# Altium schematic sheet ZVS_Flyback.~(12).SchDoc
size 431 x 279 mm; Date: Not shown in title block; ApprovedBy: Not shown in title block; CheckedBy: Not shown in title block; Author: Not shown in title block; CompanyName: Not shown in title block; Engineer: Not shown in title block; Organization: Not shown in title block; Address1: Not shown in title block; Address2: Not shown in title block; Address3: Not shown in title block; Address4: Not shown in title block; DocumentNumber: 2; Revision: Use project parameter SCH_Rev; SheetNumber: 2; SheetTotal: 2; PageSetup: Record=PageOptions¦CenterHorizontal=True¦CenterVertical=True¦PrintScale=1.00¦XCorrection=1.00¦YCorrection=1.00¦PrintKind=0¦BorderSize=5000000¦LeftOffset=0¦BottomOffset=0¦Orientation=2¦PaperLength=1000¦PaperWidth=1000¦Scale=100¦PaperSource=15¦PrintQuality=600¦MediaType=1¦DitherType=10¦PaperKind=Letter¦PrintScaleMode=1
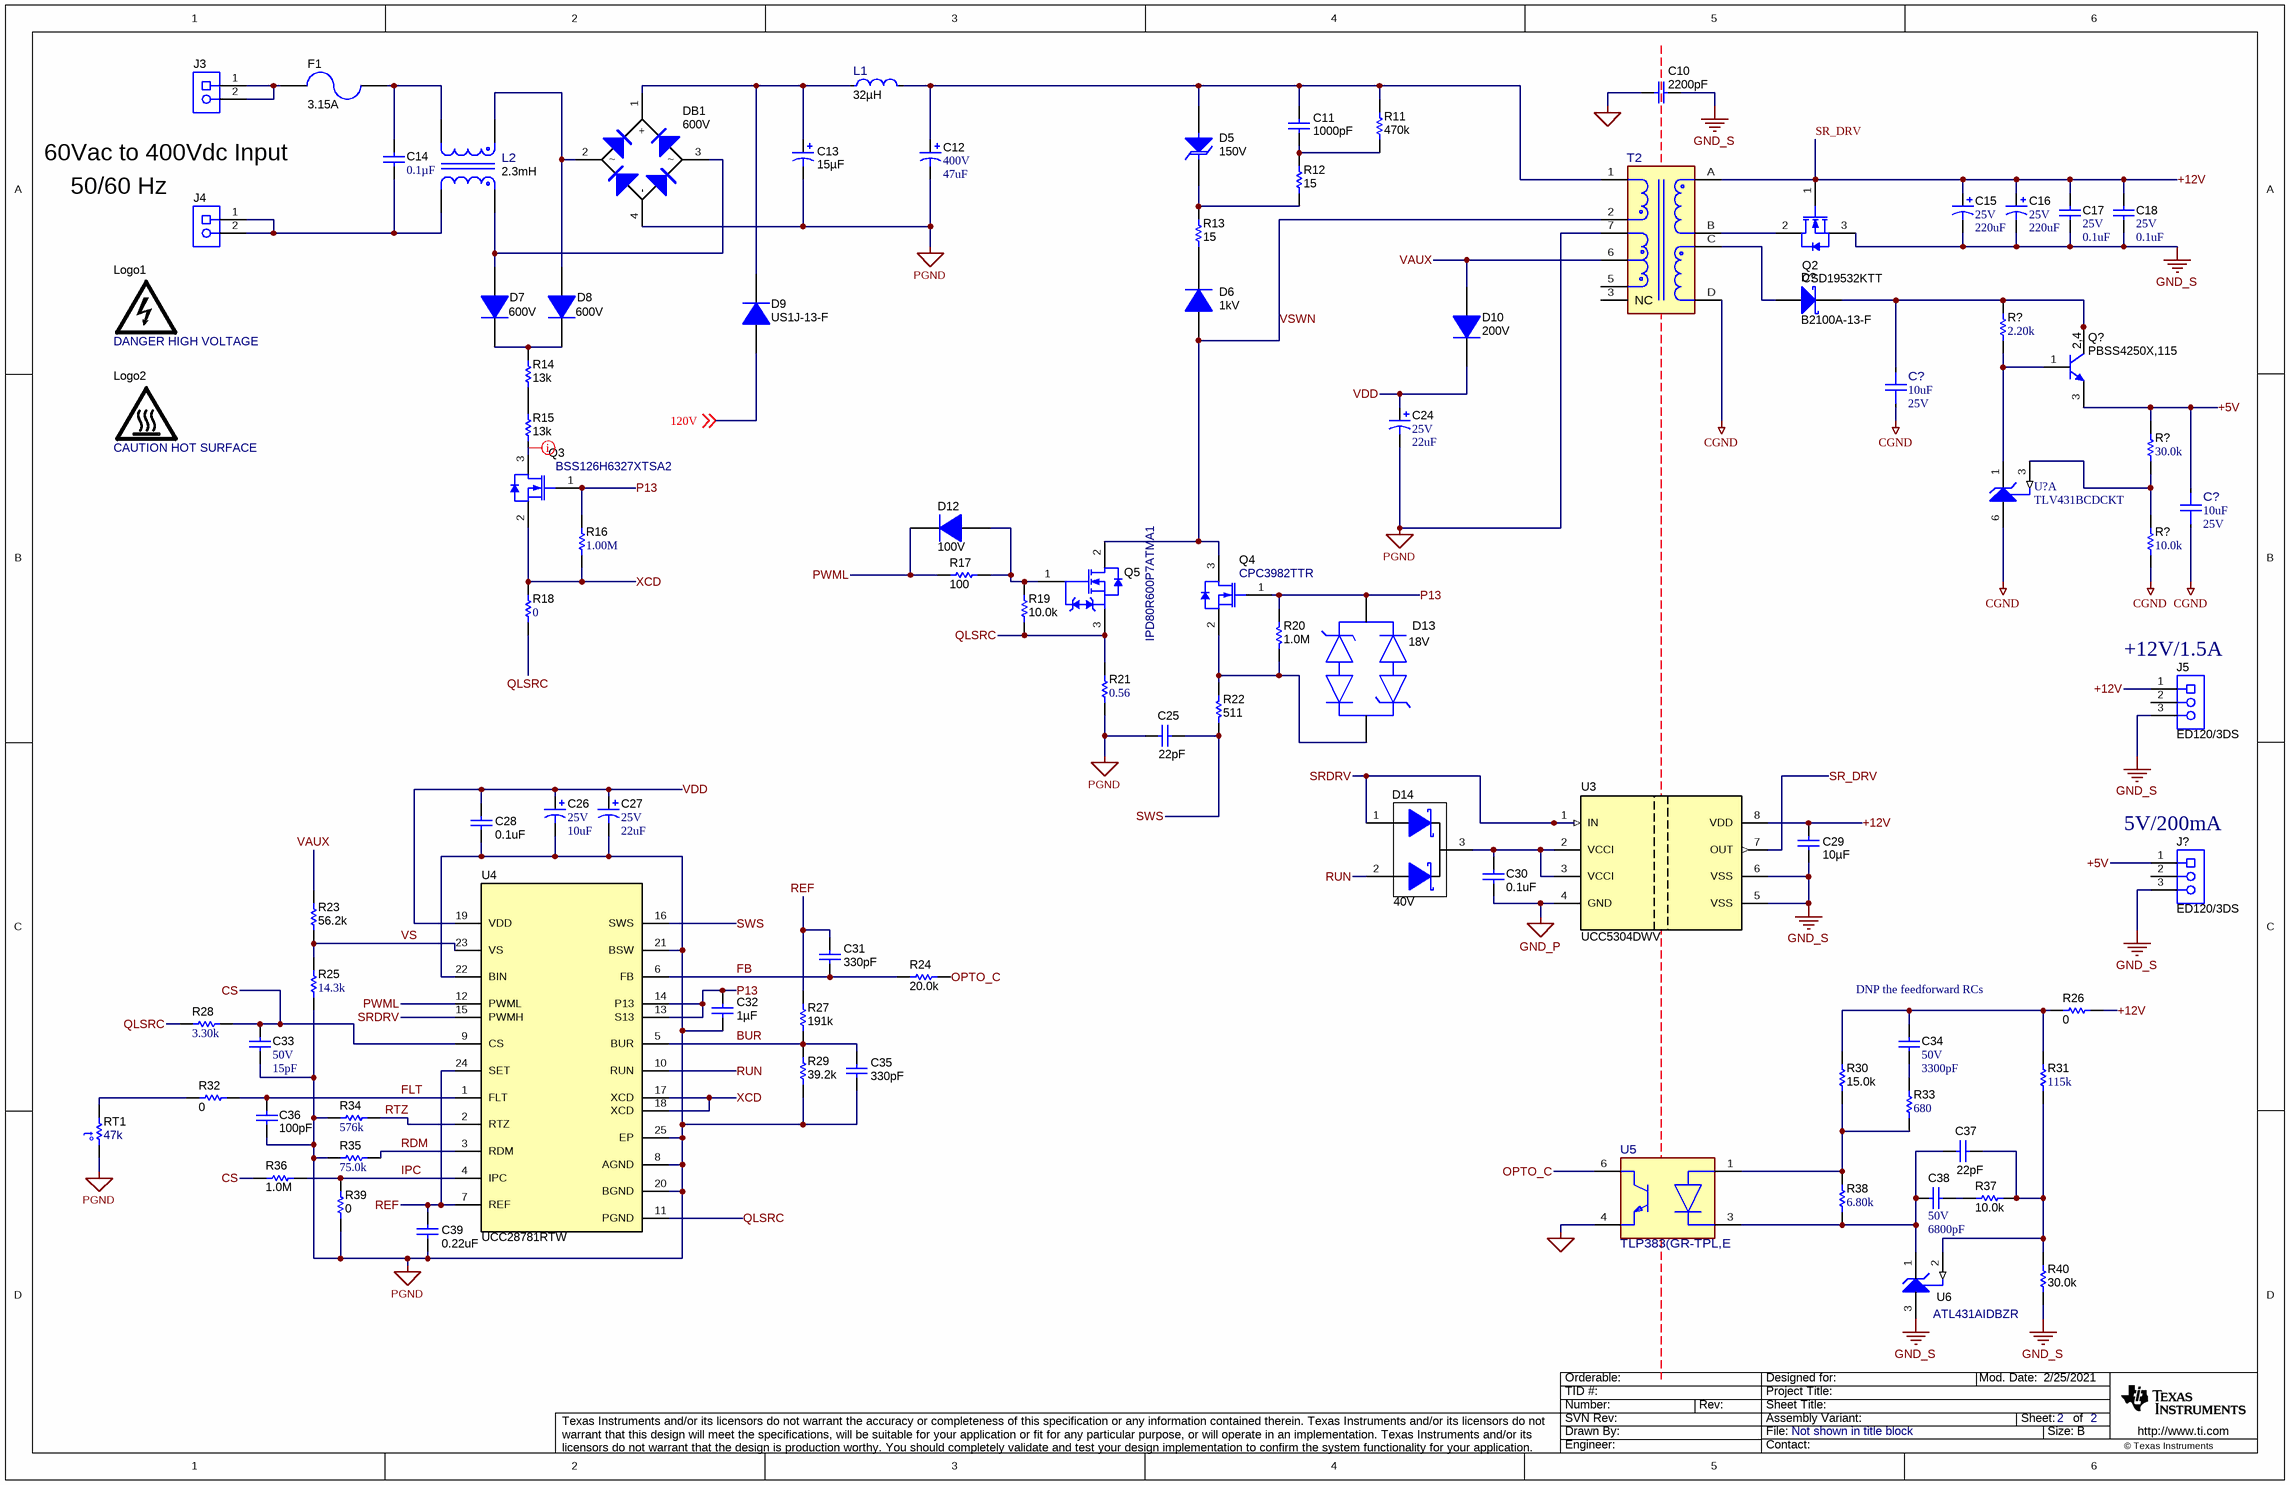
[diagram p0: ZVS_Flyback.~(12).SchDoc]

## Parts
(Parts that share a designator on the sheet are numbered #1, #2 ... from top to bottom, then left to right.)
C10  ValueDisplayed: 2200pF  [C900_9x13]  (hidden comment: C921U222MVVDBA7317)
C11  ValueDisplayed: 1000pF  [1206L]  (hidden comment: GRM31BR72J102KW01L)
C12  VDC_V: 400V  ValueDisplayed: 47uF  [CAPPR7.5-16x25]  (hidden comment: UCS2G470MHD)
C13  ValueDisplayed: 15µF  [UVC_1000x1600]  (hidden comment: UVC2G150MPD)
C14  ValueDisplayed: 0.1µF  [B32933_600x1500x2650]  (hidden comment: B32933A3104K000)
C15  VDC_V: 25V  ValueDisplayed: 220uF  [BT_1000x1250]  (hidden comment: UBT1E221MPD1TD)
C16  VDC_V: 25V  ValueDisplayed: 220uF  [BT_1000x1250]  (hidden comment: UBT1E221MPD1TD)
C17  VDC_V: 25V  ValueDisplayed: 0.1uF  [0603]  (hidden comment: 06033D104KAT2A)
C18  VDC_V: 25V  ValueDisplayed: 0.1uF  [0603]  (hidden comment: 06033D104KAT2A)
C24  VDC_V: 25V  ValueDisplayed: 22uF  [SM_RADIAL_D]  (hidden comment: EEE-FC1E220P)
C25  ValueDisplayed: 22pF  [0402S]  (hidden comment: GCM1555C1H220JA16D)
C26  VDC_V: 25V  ValueDisplayed: 10uF  [CAPSMT_62_D55]  (hidden comment: EMVA250ADA100MD55G)
C27  VDC_V: 25V  ValueDisplayed: 22uF  [SM_RADIAL_D]  (hidden comment: EEE-FC1E220P)
C28  ValueDisplayed: 0.1uF  [0402S]  (hidden comment: GRM155R71H104ME14D)
C29  ValueDisplayed: 10µF  [1206_180L]  (hidden comment: C1206C106J3RACAUTO)
C30  ValueDisplayed: 0.1uF  [0402S]  (hidden comment: GRM155R71H104ME14D)
C31  ValueDisplayed: 330pF  [0402S]  (hidden comment: GRM155R71H331KA01D)
C32  Cap_F: 1µF  [0603S]  (hidden comment: CGA3E1X7R1V105K080AC)
C33  VDC_V: 50V  ValueDisplayed: 15pF  [0402]  (hidden comment: CC0402JRNPO9BN150)
C34  VDC_V: 50V  ValueDisplayed: 3300pF  [0402]  (hidden comment: GRM155R71H332KA01D)
C35  ValueDisplayed: 330pF  [0402S]  (hidden comment: GRM155R71H331KA01D)
C36  ValueDisplayed: 100pF  [0402S]  (hidden comment: GRM1555C1H101JA01D)
C37  ValueDisplayed: 22pF  [0402S]  (hidden comment: GCM1555C1H220JA16D)
C38  VDC_V: 50V  ValueDisplayed: 6800pF  [0402]  (hidden comment: GRM155R71H682KA88D)
C39  ValueDisplayed: 0.22uF  [0402S]  (hidden comment: GRM155R71C224KA12D)
C?#1  ValueDisplayed: 10uF  VDC_V: 25V  [FP-ZRB18AR61E106ME01L_0603-MFG]  (hidden comment: ZRB18AR61E106ME01L)
C?#2  ValueDisplayed: 10uF  VDC_V: 25V  [FP-ZRB18AR61E106ME01L_0603-MFG]  (hidden comment: ZRB18AR61E106ME01L)
D5  VRWM: 150V  [SMA]  (hidden comment: SMAJ150A)
D6  Vr_V: 1kV  [SMA]  (hidden comment: MRA4007T3G)
D7  Vr_V: 600V  [TUMD2SM]  (hidden comment: RFU02VSM6STR)
D8  Vr_V: 600V  [TUMD2SM]  (hidden comment: RFU02VSM6STR)
D9  US1J-13-F  [SMA]
D10  Vr_V: 200V  [SOD-123H]  (hidden comment: CSFMT104-HF)
D12  Vr_V: 100V  [SOD-323]  (hidden comment: BAS316,115)
D13  CDSOD323-T18C  [FP-CDSOD323-T18C_SOD323-MFG]  (value not drawn)
D14  Vr_V: 40V  [SOT-323]  (hidden comment: BAS40W-05-7-F)
D?  B2100A-13-F  [SMA]
DB1  value 600V  [Z4-D]  (hidden comment: Z4DGP406L-HF)
F1  Irating_A: 3.15A  [FUSE_392]  (hidden comment: 39213150000)
J3  ED120/2DS  [On-Shore_ED120_2DS]  (value not drawn)
J4  ED120/2DS  [On-Shore_ED120_2DS]  (value not drawn)
J5  ED120/3DS  [On-Shore_ED120_3DS]
J?  ED120/3DS  [On-Shore_ED120_3DS]
L1  Ind_H: 32µH  [FP-7447052_PTH_D10MM0-MFG]  (hidden comment: 7447052)
L2  Ind_H: 2.3mH  [FP-RLTI-1387_PTH_CMC_0IN38_0IN60-MFG]  (hidden comment: RLTI-1387)
Logo1  DANGER HIGH VOLTAGE  [IEC_HighVoltage_Small]  (no BOM)
Logo2  CAUTION HOT SURFACE  [IEC_HotSurface_Small]  (no BOM)
Q2  CSD19532KTT  [KTT0002A]
Q3  BSS126H6327XTSA2  [SOT-23L]
Q4  CPC3982TTR  [SOT-23L]
Q5  IPD80R600P7ATMA1  [DPAK]
Q?  PBSS4250X,115  [SOT-89-3]
R11  ValueDisplayed: 470k  [0805_HV1]  (hidden comment: CRCW0805470KJNEA)
R12  ValueDisplayed: 15  [0805_HV1]  (hidden comment: CRCW080515R0JNEA)
R13  ValueDisplayed: 15  [0805_HV1]  (hidden comment: CRCW080515R0JNEA)
R14  ValueDisplayed: 13k  [1206L]  (hidden comment: CRCW120613K0JNEA)
R15  ValueDisplayed: 13k  [1206L]  (hidden comment: CRCW120613K0JNEA)
R16  ValueDisplayed: 1.00M  [0603]  (hidden comment: MCT06030C1004FP500)
R17  ValueDisplayed: 100  [0805_HV1]  (hidden comment: CRCW0805100RJNEA)
R18  ValueDisplayed: 0  [0603]  (hidden comment: RC0603JR-070RL)
R19  ValueDisplayed: 10.0k  [0402S]  (hidden comment: CRCW040210K0FKED)
R20  ValueDisplayed: 1.0M  [0402S]  (hidden comment: CRCW04021M00JNED)
R21  ValueDisplayed: 0.56  [1206]  (hidden comment: ERJ-8RQFR56V)
R22  ValueDisplayed: 511  [0402S]  (hidden comment: CRCW0402511RFKED)
R23  ValueDisplayed: 56.2k  [0402S]  (hidden comment: CRCW040256K2FKED)
R24  ValueDisplayed: 20.0k  [0402S]  (hidden comment: CRCW040220K0FKED)
R25  ValueDisplayed: 14.3k  [0402]  (hidden comment: CRCW040214K3FKED)
R26  ValueDisplayed: 0  [0402S]  (hidden comment: RC0402JR-070RL)
R27  ValueDisplayed: 191k  [0402S]  (hidden comment: CRCW0402191KFKED)
R28  ValueDisplayed: 3.30k  [0402]  (hidden comment: RK73H1ETTP3301F)
R29  ValueDisplayed: 39.2k  [0402S]  (hidden comment: CRCW040239K2FKED)
R30  ValueDisplayed: 15.0k  [0402S]  (hidden comment: CRCW040215K0FKED)
R31  ValueDisplayed: 115k  [0402]  (hidden comment: RC1005F1153CS)
R32  ValueDisplayed: 0  [0402S]  (hidden comment: CRCW04020000Z0EDHP)
R33  ValueDisplayed: 680  [0603]  (hidden comment: RC0603FR-07680RL)
R34  ValueDisplayed: 576k  [0402]  (hidden comment: CRCW0402576KFKED)
R35  ValueDisplayed: 75.0k  [0402]  (hidden comment: CRCW040275K0FKED)
R36  ValueDisplayed: 1.0M  [0402S]  (hidden comment: CRCW04021M00JNED)
R37  ValueDisplayed: 10.0k  [0402S]  (hidden comment: CRCW040210K0FKED)
R38  ValueDisplayed: 6.80k  [0603]  (hidden comment: RC0603FR-076K8L)
R39  ValueDisplayed: 0  [0402S]  (hidden comment: CRCW04020000Z0EDHP)
R40  ValueDisplayed: 30.0k  [0402S]  (hidden comment: CRCW040230K0FKED)
R?#1  ValueDisplayed: 2.20k  [0603]  (hidden comment: RC0603FR-072K2L)
R?#2  ValueDisplayed: 30.0k  [0603]  (hidden comment: RC0603FR-0730KL)
R?#3  ValueDisplayed: 10.0k  [0402]  (hidden comment: ERJ-2RKF1002X)
RT1  value 47k  [0603S]  (hidden comment: NCP18WB473J03RB)
T2  RLTI-1324  [FP-RLTI-1324_PTH_0IN980_0IN766-MFG]  (value not drawn)
U3  UCC5304DWV  [DWV0008A]
U4  UCC28781RTW  [RTW0024B]
U5  TLP383(GR-TPL,E  [FP-TLP383(GR-TPL,E_SO6-4-MFG]
U6  ATL431AIDBZR  [DBZ0003A_L]
U?  TLV431BCDCKT  [DCK0006A_N]  (part A of 2)

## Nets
CGND: C?#1.1 C?#2.1 R?#3.1 T2.D U?.6(ANODE)
GND2: C10.2 U5.4(Emitter)
GND_P: C30.2 U3.4(GND)
GND_S: C10.1 C15.2(-) C16.2(-) C17.2 C18.2 C29.2 J5.3 J?.3 Q2.3(S) R40.2 U3.5(VSS) U3.6(VSS) U6.3(ANODE)
PGND: C12.2(-) C13.2(-) C24.2(-) C25.1 C26.2(-) C27.2(-) C28.2 C32.2 C33.2 C35.2 C36.1 C39.2 DB1.4(-) R21.1 R25.1 R29.2 R34.1 R35.1 R39.1 RT1.2 T2.7 U4.8(AGND) U4.20(BGND) U4.21(BSW) U4.22(BIN) U4.25(EP)
120V: D9.2(A) ; off-sheet 120V
+5V: C?#2.2 J?.1 Q?.3(E) R?#2.2
+12V: C15.1(+) C16.1(+) C17.1 C18.1 C29.1 J5.1 Q2.1(G) R26.1 T2.A U3.7(OUT) U3.8(VDD)  [also labelled SR_DRV]
BUR: C35.1 R27.2 R29.1 U4.5(BUR)
CS: C33.1 R28.2 R36.2 U4.9(CS)
FB: C31.2 R24.1 U4.6(FB)
FLT: C36.2 R32.2 U4.1(FLT)
IPC: R36.1 R39.2 U4.4(IPC)
OPTO_C: R24.2 U5.6(Collector)
P13: C32.1 D13.2 Q3.1(G) Q4.1(G) R16.2 R20.2 U4.13(S13) U4.14(P13)
PWML: D12.1(K) R17.1 U4.12(PWML)
QLSRC: Q5.3(S) R18.1 R19.1 R21.2 R28.1 U4.11(PGND)
RDM: R35.2 U4.3(RDM)
REF: C31.1 C39.1 R27.1 U4.7(REF) U4.24(SET)
RTZ: R34.2 U4.2(RTZ)
RUN: D14.2(A) U4.10(RUN)
SRDRV: D14.1(A) U3.1(IN) U4.15(PWMH)
SWS: C25.2 R22.1 U4.16(SWS)
VAUX: D10.2(A) R23.1 T2.6
VDD: C24.1(+) C26.1(+) C27.1(+) C28.1 D10.1(K) U4.19(VDD)
VS: R23.2 R25.2 U4.23(VS)
VSWN: D6.2(A) Q4.3(D) Q5.2(D) T2.2
XCD: Q3.2(S) R16.1 R18.2 U4.17(XCD) U4.18(XCD)
NetC11_1: C11.1 C12.1(+) D5.2(A) L1.2 R11.2 T2.1
NetC11_2: C11.2 R11.1 R12.2
NetC13_1: C13.1(+) D9.1(K) DB1.1(+) L1.1
NetC14_1: C14.1 F1.1 L2.3
NetC14_2: C14.2 J4.1 J4.2 L2.2
NetC30_1: C30.1 D14.3(K) U3.2(VCCI) U3.3(VCCI)
NetC34_1: C34.1 R26.2 R30.2 R31.2
NetC34_2: C34.2 R33.2
NetC37_1: C37.1 C38.2 R38.1 U5.3(Cathode) U6.1(CATHODE)
NetC37_2: C37.2 R31.1 R37.2 R40.1 U6.2(REF)
NetC38_1: C38.1 R37.1
NetC?#1_2: C?#1.2 D?.1(K) Q?.2(C) Q?.4(C) R?#1.2
NetD5_1: D5.1(K) R12.1 R13.2
NetD6_1: D6.1(K) R13.1
NetD7_1: D7.1(K) D8.1(K) R14.1
NetD7_2: D7.2(A) DB1.3 L2.1
NetD8_2: D8.2(A) DB1.2 L2.4
NetD12_2: D12.2(A) Q5.1(G) R17.2 R19.2
NetD13_1: D13.1 Q4.2(S) R20.1 R22.2
NetD?_2: D?.2(A) T2.C
NetF1_2: F1.2 J3.1 J3.2
NetQ2_2: Q2.2(D) T2.B
NetQ3_3: Q3.3(D) R15.2
NetQ?_1: Q?.1(B) R?#1.1 U?.1(CATHODE)
NetR14_2: R14.2 R15.1
NetR30_1: R30.1 R33.1 R38.2 U5.1(Anode)
NetR32_1: R32.1 RT1.1
NetR?#2_1: R?#2.1 R?#3.2 U?.3(REF)

Not connected (* = marked no-connect by the designer): J5 2; J? 2; T2 3(NC) 5

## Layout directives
net class HV: NetQ3_3

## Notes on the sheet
- 60Vac to 400Vdc Input
- 50/60 Hz
- (near D13) 18V
- (near J5) +12V/1.5A
- (near J?) 5V/200mA
- (near C34) DNP the feedforward RCs

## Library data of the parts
C10 = CMP-0078358-1: CAP, CERM, 2200 pF, X1 400 VAC/Y1 400 VAC, +/- 20%, Y5V, D9xL13mm; Manufacturer: Kemet; Cap_F: 2.2nF; SizeAreaWB_mm2: 121; VAC_X: 400V; SizeArea_mm2: 81; AEC Qualified: N; AEC Category: Q200; Value: 2200pF; TaMax_C: 125°C; SizeZ_mm: 13; TaMin_C: -40°C; SizeY_mm: 9; U/M: EA; AC_Safety: X1Y1; Cap_Case: 9x13mm
C11 = CMP-0008909-2: CAP, CERM, 1000 pF, 630 V, +/- 10%, X7R, 1206; Manufacturer: MuRata; TaMin_C: -55°C; Polarized: N; SizeAreaWB_mm2: 10.92; Value1: Unknown; U/M: EA; Value: 1000pF; TaMax_C: 125°C; SizeZ_mm: 1.35; SizeX_mm: 3.2; SizeY_mm: 1.6; Cap_Case: 1206; Value2: 630V; SizeArea_mm2: 5.12; Cap_F: 1nF; AEC Category: Q200
C12 = CMP-0010241-2: CAP, AL, 47 uF, 400 V, +/- 20%, TH; Manufacturer: Nichicon; TaMin_C: -40°C; Polarized: Y; SizeAreaWB_mm2: 324; Value1: Unknown; U/M: EA; Value: 47uF; TaMax_C: 105°C; SizeZ_mm: 25; SizeX_mm: 16; Cap_Case: Radial  16x25mm; SizeArea_mm2: 256; CompType: Capacitor; AEC Qualified: N; Cap_F: 47µF; IRMS_A: 1.18A; AEC Category: Q200
C13 = CMP-0860955-2: CAP, AL, 15 µF, 400 V, +/- 20%, AEC-Q200 Grade 2, TH; Manufacturer: Nichicon; SizeArea_mm2: 100; CompType: Capacitor; Value2: 400V; SizeZ_mm: 18; IRMS_A: 180mA; Polarized: Y; SizeX_mm: 10; Value: 15uF; TaMin_C: -40°C; AEC Grade: 2; U/M: EA; SizeAreaWB_mm2: 144; Cap_Case: 10x16; TaMax_C: 105°C; AEC Category: Q200
C14 = CMP-0077664-2: CAP, Film, 0.1 µF, X2 305 VAC, +/- 10%, AEC-Q200 Grade 2, TH; Manufacturer: TDK; TaMin_C: -40°C; Polarized: N; SizeAreaWB_mm2: 210.0; Value: 0.1uF; TaMax_C: 105°C; VAC_X: 305; SizeZ_mm: 15.0; SizeX_mm: 26.0; SizeY_mm: 5.5; SizeArea_mm2: 143.0; AEC Qualified: Y; Cap_F: 100nF; AEC Grade: 2; AEC Category: Q200
C15 C16 = CMP-0010527-1: CAP, AL, 220 uF, 25 V, +/- 20%, 0.1 ohm, TH; Manufacturer: Nichicon; TaMin_C: -40°C; ESR_ohm: 1d; Polarized: Y; SizeAreaWB_mm2: 144; Value1: 0.1 ohm; U/M: EA; Value: 220uF; TaMax_C: 125°C; SizeZ_mm: 14.5; SizeX_mm: 10; Cap_Case: 10x12.5mm; SizeArea_mm2: 100; CompType: Capacitor; Cap_F: 220µF; IRMS_A: 6.8dA; AEC Category: Q200
C17 C18 = CMP-0006758-5: CAP, CERM, 0.1 uF, 25 V, +/- 10%, X5R, 0603; Manufacturer: AVX; TaMin_C: -55°C; ESR_ohm: 0.048; Polarized: N; SizeAreaWB_mm2: 4.68; Value1: 0.048 ohm; U/M: EA; Value: 0.1uF; TaMax_C: 85°C; SizeZ_mm: 1; SizeX_mm: 1.6; SizeY_mm: 0.8; SizeArea_mm2: 1.28; Cap_F: 100nF; IRMS_A: 5.3dA; AEC Category: Q200
C24 C27 = CMP-0010654-1: CAP, AL, 22 uF, 25 V, +/- 20%, 1 ohm, SMD; Manufacturer: Panasonic; TaMin_C: -40°C; ESR_ohm: 1; Polarized: Y; SizeAreaWB_mm2: 84.28; Value1: 1 ohm; U/M: EA; Value: 22uF; TaMax_C: 105°C; SizeZ_mm: 5.4; SizeX_mm: 7.8; SizeY_mm: 6.6; Cap_Case: D; SizeArea_mm2: 51.48; CompType: Capacitor; Cap_F: 22µF; IRMS_A: 1.15dA; AEC Category: Q200
C25 C37 = CMP-0006348-2: CAP, CERM, 22 pF, 50 V, +/- 5%, C0G/NP0, AEC-Q200 Grade 1, 0402; Manufacturer: MuRata; TaMin_C: -55°C; Polarized: N; SizeAreaWB_mm2: 3; Value1: Unknown; U/M: EA; Value: 22pF; TaMax_C: 125°C; SizeZ_mm: 0.6; SizeX_mm: 1; SizeY_mm: 0.5; Cap_Case: 0402; Value2: 50V; AEC Qualified: Y; AEC Category: Q200
C26 = CMP-0010785-1: CAP, AL, 10 uF, 25 V, +/- 20%, SMD; Manufacturer: Chemi-Con; TaMin_C: -40°C; Polarized: Y; SizeAreaWB_mm2: 28.09; Value1: Unknown; U/M: EA; Value: 10uF; TaMax_C: 85°C; SizeZ_mm: 5.2; SizeX_mm: 4.3; Cap_Case: D55; SizeArea_mm2: 18.49; CompType: Capacitor; Cap_F: 10µF; IRMS_A: 24mA; AEC Category: Q200
C28 C30 = CMP-0006675-2: CAP, CERM, 0.1 uF, 50 V, +/- 20%, X7R, 0402; Manufacturer: MuRata; TaMin_C: -55°C; Polarized: N; SizeAreaWB_mm2: 3; Value1: Unknown; U/M: EA; Value: 0.1uF; TaMax_C: 125°C; SizeZ_mm: 0.6; SizeX_mm: 1; SizeY_mm: 0.5; Cap_Case: 0402; Value2: 50V; Cap_F: 100nF; AEC Category: Q200
C29 = CMP-0081062-1: CAP, CERM, 10 µF, 25 V,+/- 5%, X7R, AEC-Q200 Grade 1, 1206; Manufacturer: Kemet; TaMin_C: -55°C; Polarized: N; SizeAreaWB_mm2: 10.92; U/M: EA; Value: 10uF; TaMax_C: 125°C; SizeZ_mm: 1.8; SizeX_mm: 3.2; SizeY_mm: 1.6; Cap_Case: 1206_180; Value2: 25V; SizeArea_mm2: 5.12; AEC Qualified: Y; AEC Grade: 1; AEC Category: Q200
C31 C35 = CMP-0006687-2: CAP, CERM, 330 pF, 50 V, +/- 10%, X7R, 0402; Manufacturer: MuRata; TaMin_C: -55°C; Polarized: N; SizeAreaWB_mm2: 3; Value1: Unknown; U/M: EA; Value: 330pF; TaMax_C: 125°C; SizeZ_mm: 0.6; SizeX_mm: 1; SizeY_mm: 0.5; Cap_Case: 0402; Value2: 50V; AEC Category: Q200
C32 = CMP-0007067-4: CAP, CERM, 1 uF, 35 V, +/- 10%, X7R, AEC-Q200 Grade 1, 0603; Manufacturer: TDK; TaMin_C: -55°C; ESR_ohm: 5.522m; Polarized: N; SizeAreaWB_mm2: 4.68; Value1: 0.005522 ohm; U/M: EA; Value: 1uF; TaMax_C: 125°C; SizeZ_mm: 1; SizeX_mm: 1.6; SizeY_mm: 0.8; Cap_Case: 0603; Value2: 35V; SizeArea_mm2: 1.28; AEC Qualified: Y; IRMS_A: 2.21617A; AEC Category: Q200
C33 = CMP-0006304-2: CAP, CERM, 15 pF, 50 V, +/- 5%, C0G/NP0, 0402; Manufacturer: Yageo America; TaMin_C: -55°C; Polarized: N; SizeAreaWB_mm2: 3; Value1: Unknown; U/M: EA; Value: 15pF; TaMax_C: 125°C; SizeZ_mm: 0.6; SizeX_mm: 1; SizeY_mm: 0.5; AEC Category: Q200
C34 = CMP-0006688-2: CAP, CERM, 3300 pF, 50 V, +/- 10%, X7R, 0402; Manufacturer: MuRata; TaMin_C: -55°C; Polarized: N; SizeAreaWB_mm2: 3; Value1: Unknown; U/M: EA; Value: 3300pF; TaMax_C: 125°C; SizeZ_mm: 0.6; SizeX_mm: 1; SizeY_mm: 0.5; Cap_F: 3.3nF; AEC Category: Q200
C36 = CMP-0006410-2: CAP, CERM, 100 pF, 50 V, +/- 5%, C0G/NP0, 0402; Manufacturer: MuRata; TaMin_C: -55°C; Polarized: N; SizeAreaWB_mm2: 3; Value1: Unknown; U/M: EA; Value: 100pF; TaMax_C: 125°C; SizeZ_mm: 0.6; SizeX_mm: 1; SizeY_mm: 0.5; Cap_Case: 0402; Value2: 50V; AEC Category: Q200
C38 = CMP-0006696-2: CAP, CERM, 6800 pF, 50 V, +/- 10%, X7R, 0402; Manufacturer: MuRata; TaMin_C: -55°C; Polarized: N; SizeAreaWB_mm2: 3; Value1: Unknown; U/M: EA; Value: 6800pF; TaMax_C: 125°C; SizeZ_mm: 0.6; SizeX_mm: 1; SizeY_mm: 0.5; Cap_F: 6.8nF; AEC Category: Q200
C39 = CMP-0006648-2: CAP, CERM, 0.22 uF, 16 V, +/- 10%, X7R, 0402; Manufacturer: MuRata; TaMin_C: -55°C; Polarized: N; SizeAreaWB_mm2: 3; Value1: Unknown; U/M: EA; Value: 0.22uF; TaMax_C: 125°C; SizeZ_mm: 0.6; SizeX_mm: 1; SizeY_mm: 0.5; Cap_Case: 0402; Value2: 16V; Cap_F: 220nF; AEC Category: Q200
C?#1 C?#2 = CMP-0094458-1: 10µF ±20% 25V Ceramic Capacitor X5R 0603 (1608 Metric); Manufacturer: Murata Electronics; SizeZ_mm: 1.2mm; AEC Qualified: No
D5 = CMP-0084982-1: Diode, TVS, Uni, 150 V, 243 Vc, 400 W, 1.6 A, SMA; Manufacturer: Littelfuse; Vc: 243V; Ipp: 1.6A; RJA_CperW: 120; AEC Qualified: N; Value: 150V; Ppk: 400W; AEC Category: Q101; SizeArea_mm2: 16.3228; SizeAreaWB_mm2: 37.3428; SizeZ_mm: 2.87; Vbr_Max: 185V; SizeX_mm: 5.59; SizeY_mm: 2.92; Vbr_Min: 167V
D6 = CMP-0077082-2: Diode, Standard Recovery Rectifier, 1000 V, 1 A, AEC-Q101, SMA; Manufacturer: ON Semiconductor; SizeAreaWB_mm2: 37.3428; SizeArea_mm2: 16.3228; AEC Qualified: Y; TJmax_C: 175°C; AEC Category: Q101; Value: 1000V; SizeZ_mm: 2.87; Green_REACh: Passed; Io_A: 1A; Vf_V: 1.1V; SizeY_mm: 2.92; Green_Lifecycle: Active; SizeX_mm: 5.59; RJC_CperW: 16.2
D7 D8 = CMP-0080762-2: Diode, Standard Recovery Rectifier, 600 V, 0.2 A, 2x1.4mm; Manufacturer: Rohm; SizeArea_mm2: 3.5; AEC Qualified: N; SizeY_mm: 1.4; Io_A: 200mA; SizeZ_mm: 0.8; Vf_V: 2.2V; SizeAreaWB_mm2: 8.4; TJmax_C: 150°C; Value1: 0.2A; SizeX_mm: 2.5; AEC Category: Q101; Value: 600V
D9 = CMP-0077027-2: Diode, Ultrafast, 600 V, 1 A, SMA; Manufacturer: Diodes Inc.; Value: 600V; TJmax_C: 150°C; Value1: 1A; Value2: 1.7V; SizeY_mm: 2.92; Green_REACh: Passed; Green_Lifecycle: Active; SizeX_mm: 5.59; AEC Category: Q101; SizeAreaWB_mm2: 37.3428; SizeZ_mm: 2.87; SizeArea_mm2: 16.3228
D10 = CMP-0029199-2: Diode, Superfast Rectifier, 200 V, 1 A, 3.5x1.6mm; Manufacturer: Comchip Technology; Vf_V: 950mV; Value: 200V; Value1: 1A; Value2: 0.95V; TJmax_C: 150°C; SizeAreaWB_mm2: 11.7; SizeArea_mm2: 5.6; SizeX_mm: 3.5; SizeY_mm: 1.6; SizeZ_mm: 1; AEC Category: Q101; AEC Qualified: N
D12 = CMP-0029006-2: Diode, Ultrafast, 100 V, 0.25 A, SOD-323; Manufacturer: Nexperia; SizeY_mm: 1.35; Value1: 0.25A; SizeAreaWB_mm2: 8.695; SizeZ_mm: 1; Io_A: 250mA; Value2: 1.4V; SizeX_mm: 2.7; Green_REACh: Incomplete; TJmax_C: 150°C; Green_Lifecycle: Not Set; AEC Category: Q101; Value: 100V; SizeArea_mm2: 3.645
D13 = CMP-0087587-1: Diode, TVS, Bi, 18 V, SOD-323; Manufacturer: Bourns Inc.; SizeZ_mm: 1.14mm; AEC Qualified: No
D14 = CMP-0028437-2: Diode, Schottky, 40 V, 0.2 A, SOT-323; Manufacturer: Diodes Inc.; Io_A: 200mA; Green_Lifecycle: Not Set; SizeAreaWB_mm2: 10.24; Green_REACh: Incomplete; Value1: 0.2A; Value: 40V; SizeZ_mm: 1.1; SizeX_mm: 2.2; Vf_V: 800mV; Value2: 0.8V; SizeArea_mm2: 4.84; AEC Category: Q101
D? = CMP-0081099-2: Diode, Schottky, 100 V, 2 A, SMA; Manufacturer: Diodes Inc.; SizeZ_mm: 2.87; SizeX_mm: 5.59; AEC Qualified: N; Value2: 0.79V; SizeArea_mm2: 16.3228; Vf_V: 790mV; AEC Category: Q101; TJmax_C: 125°C; Vr_V: 100V; Value: 100V; Io_A: 2A; SizeAreaWB_mm2: 37.3428; SizeY_mm: 2.92
DB1 = Z4DGP406L-HF: Diode, P-N-Bridge, 600 V, 4 A, Z4-D; Manufacturer: Comchip Technology; U/M: EA; Vf_V: 0.95; Value1: 4A; Value2: 0.95V; Io_A: 4; Vr_V: 600; TJmax_C: 175; SizeAreaWB_mm2: 126.25; SizeArea_mm2: 85.05; SizeX_mm: 10.5; SizeY_mm: 8.1; SizeZ_mm: 1.55; AEC Category: Q101; AEC Qualified: N; Green_Lifecycle: Not Set; Green_REACh: Incomplete
F1 = CMP-0003561-2: Fuse, 3.15 A, 250VAC/VDC, TH; Manufacturer: Littelfuse; VAC_V: 250V
J3 J4 = CMP-0074910-1: Terminal Block, 5.08 mm, 2x1, Brass, TH; Manufacturer: On-Shore Technology; Pitch_mm: 5.08; Gender: Female; Shrouded: N; Row_Count: 1; Current_A: 15A; Voltage_V: 300V; Cert_CULUS: Y; CNHeader: False; CT: True; Green_Lifecycle: Not Set; Green_REACh: Incomplete
J5 J? = CMP-0074911-1: Terminal Block, 5.08 mm, 3x1, Brass, TH; Manufacturer: On-Shore Technology; Cert_VDE: Y; CNHeader: False; Current_A: 15A; Green_Lifecycle: Not Set; Shrouded: N; Gender: Female; Green_REACh: Incomplete; Voltage_V: 300V; Row_Count: 1; Pitch_mm: 5.08; CT: True
L1 = CMP-0087546-1: WE-FI Leaded Toroidal Line Choke; Manufacturer: Wurth; SizeZ_mm: 10mm; Irms: 2.6A; DCR_ohm: 0.045; AEC Qualified: No; Symbol Name: SYM-7447052
L2 = CMP-0092946-1: Common Mode Choke, 2.3mH 35%, 0.6x0.38x0.75 IN; Manufacturer: Renco; Test Frequency: 10kHz; SizeZ_mm: 0.75inch; DCR_ohm: 0.03; AEC Qualified: No
Logo1 = CMP-0074835-1: IEC 61010-1 High Voltage Warning; SymbolCreator: a0412235
Logo2 = CMP-0074837-1: IEC 61010-1 Hot Surface Warning; SymbolCreator: a0412235
Q2 = CMP-0000957-3: MOSFET, N-CH, 100 V, 136 A, KTT0002A (TO-263-2); Alternate Manufacturer: None; Manufacturer: Texas Instruments; SizeZ_mm: 4.7; ChType: N; Value2: 44 nC; VdsMax_V: 100V; SizeX_mm: 14.3; SizeAreaWB_mm2: 198.208; SizeY_mm: 10.16; Vgs_V: 20V; QgTyp_nC: 44; Value: 100V; SizeArea_mm2: 145.288; AEC Category: Q101; IdsMax_A: 136A
Q3 = CMP-0067574-2: MOSFET, N-CH, Depletion Mode, 100 V, 0.17 A, AEC-Q101, SOT-23; Manufacturer: Infineon Technologies; Alternate Manufacturer: None; ChType: N; Value: 600V; Value1: ? ohm; Value2: 1.4 nC; QgTyp_nC: 1.4; Vgs_V: 20V; IdsMax_A: 21mA; SizeAreaWB_mm2: 14.0; SizeArea_mm2: 7.5; SizeX_mm: 2.5; SizeY_mm: 3.0; SizeZ_mm: 1.1; AEC Category: Q101; AEC Qualified: Y
Q4 = CMP-0081263-2: MOSFET, N-CH, Depletion Mode, 800 V, SOT-23; Alternate Manufacturer: None; Manufacturer: IXYS; SizeAreaWB_mm2: 14; Vgs_V: 15V; Value1: ? ohm; VdsMax_V: 800V; Value: 800V; SizeZ_mm: 1.1; SizeX_mm: 2.5; SizeY_mm: 3; Value2: ? nC; SizeArea_mm2: 7.5; ChType: N; AEC Category: Q101
Q5 = CMP-0083711-2: MOSFET, N-CH, 800 V, 8 A, DPAK; Manufacturer: Infineon Technologies; Alternate Manufacturer: None; AEC Qualified: N; Vgs_V: 20V; SizeY_mm: 6.54; VdsMax_V: 800V; IdsMax_A: 8A; SizeX_mm: 9.91; Value2: 20 nC; AEC Category: Q101; ChMode: Enhancement; SizeAreaWB_mm2: 101.7114; Value1: ? ohm; SizeArea_mm2: 64.8114; Value: 800V; SizeZ_mm: 2.29; QgTyp_nC: 20
Q? = CMP-0000491-2: Transistor, NPN, 50 V, 2 A, SOT-89; Manufacturer: NXP Semiconductor; TaMax_C: 150°C; Value1: 2 A; Vcesat1_V: 2.5dV; SizeX_mm: 4.1; SizeY_mm: 4.5; TaMin_C: -65°C; IcRated_A: 2A; CompType: BJT; SizeZ_mm: 1.5; AEC Qualified: N; Value: 50 V; SizeArea_mm2: 18.45; NPN: 1; Vceo_V: 50V; PNP: 0; AEC Category: Q101; SizeAreaWB_mm2: 28.05; U/M: EA
R11 = CMP-0020554-3: RES, 470 k, 5%, 0.125 W, AEC-Q200 Grade 0, 0805; Manufacturer: Vishay-Dale; Power_W: 125mW; TempCo: 200 ppm/C; Value: 470k; EIA_Code: E24; SizeX_mm: 2; SizeY_mm: 1.25; SizeZ_mm: 1.45; Value2: 0.125W; SizeArea_mm2: 2.5; AEC Qualified: Y; VDC_V: 150V; AEC Category: Q200; AEC Grade: 0
R12 R13 = CMP-0020464-3: RES, 15, 5%, 0.125 W, AEC-Q200 Grade 0, 0805; Manufacturer: Vishay-Dale; Power_W: 125mW; TempCo: 200 ppm/C; Value_Code: 15R0; Value: 15; EIA_Code: E24; SizeX_mm: 2; SizeY_mm: 1.25; SizeZ_mm: 1.45; Value2: 0.125W; SizeArea_mm2: 2.5; AEC Qualified: Y; VDC_V: 150V; AEC Category: Q200; AEC Grade: 0
R14 R15 = CMP-0018589-3: RES, 13 k, 5%, 0.25 W, AEC-Q200 Grade 0, 1206; Manufacturer: Vishay-Dale; Power_W: 250mW; TempCo: 200 ppm/C; Value_Code: 13k0; Value: 13k; EIA_Code: E24; SizeX_mm: 3.2; SizeY_mm: 1.6; SizeZ_mm: 1.35; Value2: 0.25W; SizeArea_mm2: 5.12; AEC Qualified: Y; VDC_V: 200V; AEC Category: Q200; AEC Grade: 0
R16 = CMP-0022731-2: RES, 1.00 M, 1%, 0.125 W, 0603; Manufacturer: Vishay/Beyschlag; Power_W: 125mW; TempCo: 50 ppm/C; Value_Code: 1M00; U/M: EA; Value: 1.00Meg; EIA_Code: E96; Res_ohm: 1M; SizeX_mm: 1.6; SizeY_mm: 0.8; SizeZ_mm: 1; Value2: 0.125W; SizeArea_mm2: 1.28; AEC Qualified: N; VDC_V: 75V; AEC Category: Q200
R17 = CMP-0020445-3: RES, 100, 5%, 0.125 W, AEC-Q200 Grade 0, 0805; Manufacturer: Vishay-Dale; Power_W: 125mW; TempCo: 200 ppm/C; Value_Code: 100R; Value: 100; EIA_Code: E24; SizeX_mm: 2; SizeY_mm: 1.25; SizeZ_mm: 1.45; Value2: 0.125W; SizeArea_mm2: 2.5; AEC Qualified: Y; VDC_V: 150V; AEC Category: Q200; AEC Grade: 0
R18 = CMP-0025885-5: RES, 0, 5%, 0.1 W, 0603; Manufacturer: Yageo; Power_W: 100mW; TempCo: 200 ppm/C; Value_Code: 0000; Value: 0; EIA_Code: E24; SizeX_mm: 1.6; SizeZ_mm: 1; Value2: 0.1W; SizeArea_mm2: 1.28; AEC Qualified: N; VDC_V: 75V; AEC Category: Q200; SizeY_mm: 0.8; SizeAreaWB_mm2: 4.68
R19 R37 = CMP-0025958-3: RES, 10.0 k, 1%, 0.063 W, AEC-Q200 Grade 0, 0402; Manufacturer: Vishay-Dale; Power_W: 63mW; TempCo: 100 ppm/C; Value_Code: 10k0; Value: 10.0k; EIA_Code: E96; Res_ohm: 10k; SizeX_mm: 1; SizeY_mm: 0.5; SizeZ_mm: 0.6; Value2: 0.063W; AEC Qualified: Y; VDC_V: 50V; AEC Category: Q200; AEC Grade: 0
R20 = CMP-0026859-2: RES, 1.0 M, 5%, 0.063 W, AEC-Q200 Grade 0, 0402; Manufacturer: Vishay-Dale; Value: 1.0Meg; Res_ohm: 1M; Value_Code: 1M00; Power_W: 63mW; Value2: 0.063W; VDC_V: 50V; TempCo: 200 ppm/C; SizeArea_mm2: 0.5; SizeX_mm: 1; SizeZ_mm: 0.6; EIA_Code: E24; AEC Category: Q200; AEC Qualified: Y; AEC Grade: 0
R21 = CMP-0017792-3: RES, 0.56, 1%, 0.25 W, AEC-Q200 Grade 0, 1206; Manufacturer: Panasonic; Power_W: 250mW; TempCo: 250 ppm/C; Value_Code: R560; Value: 0.56; EIA_Code: E96; SizeX_mm: 3.2; SizeY_mm: 1.6; SizeZ_mm: 1.35; Value2: 0.25W; SizeArea_mm2: 5.12; AEC Qualified: Y; AEC Category: Q200; AEC Grade: 0; SizeAreaWB_mm2: 10.92
R22 = CMP-0026436-2: RES, 511, 1%, 0.063 W, AEC-Q200 Grade 0, 0402; Manufacturer: Vishay-Dale; Power_W: 63mW; TempCo: 100 ppm/C; Value_Code: 511R; Value: 511; EIA_Code: E96; SizeX_mm: 1; SizeY_mm: 0.5; SizeZ_mm: 0.6; Value2: 0.063W; AEC Qualified: Y; VDC_V: 50V; AEC Category: Q200; AEC Grade: 0
R23 = CMP-0026453-2: RES, 56.2 k, 1%, 0.063 W, AEC-Q200 Grade 0, 0402; Manufacturer: Vishay-Dale; Power_W: 63mW; TempCo: 100 ppm/C; Value_Code: 56k2; Value: 56.2k; EIA_Code: E96; SizeX_mm: 1; SizeY_mm: 0.5; SizeZ_mm: 0.6; Value2: 0.063W; AEC Qualified: Y; VDC_V: 50V; AEC Category: Q200; AEC Grade: 0
R24 = CMP-0026162-2: RES, 20.0 k, 1%, 0.063 W, AEC-Q200 Grade 0, 0402; Manufacturer: Vishay-Dale; Power_W: 63mW; TempCo: 100 ppm/C; Value_Code: 20k0; Value: 20.0k; EIA_Code: E96; Res_ohm: 20k; SizeX_mm: 1; SizeY_mm: 0.5; SizeZ_mm: 0.6; Value2: 0.063W; AEC Qualified: Y; VDC_V: 50V; AEC Category: Q200; AEC Grade: 0
R25 = CMP-0026016-3: RES, 14.3 k, 1%, 0.063 W, AEC-Q200 Grade 0, 0402; Manufacturer: Vishay-Dale; Power_W: 63mW; TempCo: 100 ppm/C; Value_Code: 14k3; Value: 14.3k; EIA_Code: E96; SizeX_mm: 1; SizeY_mm: 0.5; SizeZ_mm: 0.6; Value2: 0.063W; AEC Qualified: Y; VDC_V: 50V; AEC Category: Q200; AEC Grade: 0
R26 = CMP-0027004-2: RES, 0, 5%, 0.063 W, 0402; Manufacturer: Yageo America; Power_W: 63mW; TempCo: 200 ppm/C; Value_Code: 0000; U/M: EA; Value: 0; EIA_Code: E24; SizeX_mm: 1; SizeY_mm: 0.5; SizeZ_mm: 0.6; Value2: 0.063W; VDC_V: 50V; AEC Category: Q200
R27 = CMP-0026063-3: RES, 191 k, 1%, 0.063 W, AEC-Q200 Grade 0, 0402; Manufacturer: Vishay-Dale; Power_W: 63mW; TempCo: 100 ppm/C; Value: 191k; EIA_Code: E96; SizeX_mm: 1; SizeY_mm: 0.5; SizeZ_mm: 0.6; Value2: 0.063W; AEC Qualified: Y; VDC_V: 50V; AEC Category: Q200; AEC Grade: 0
R28 = CMP-0026750-1: RES, 3.30 k, 1%, 0.063 W, AEC-Q200 Grade 0, 0402; Manufacturer: KOA Speer; Power_W: 63mW; TempCo: 100 ppm/C; Value_Code: 3k30; U/M: EA; Value: 3.30k; Res_ohm: 3.3k; SizeX_mm: 1; SizeY_mm: 0.5; SizeZ_mm: 0.6; Value2: 0.063W; AEC Qualified: Y; VDC_V: 50V; AEC Grade: 0; AEC Category: Q200
R29 = CMP-0026327-2: RES, 39.2 k, 1%, 0.063 W, AEC-Q200 Grade 0, 0402; Manufacturer: Vishay-Dale; Power_W: 63mW; TempCo: 100 ppm/C; Value_Code: 39k2; Value: 39.2k; EIA_Code: E96; SizeX_mm: 1; SizeY_mm: 0.5; SizeZ_mm: 0.6; Value2: 0.063W; AEC Qualified: Y; VDC_V: 50V; AEC Category: Q200; AEC Grade: 0
R30 = CMP-0026027-3: RES, 15.0 k, 1%, 0.063 W, AEC-Q200 Grade 0, 0402; Manufacturer: Vishay-Dale; Power_W: 63mW; TempCo: 100 ppm/C; Value_Code: 15k0; Value: 15.0k; EIA_Code: E96; Res_ohm: 15k; SizeX_mm: 1; SizeY_mm: 0.5; SizeZ_mm: 0.6; Value2: 0.063W; AEC Qualified: Y; VDC_V: 50V; AEC Category: Q200; AEC Grade: 0
R31 = CMP-0077547-1: RES, 115 k, 1%, 0.0625 W, 0402; Manufacturer: Samsung Electro-Mechanics; Power_W: 62.5mW; TempCo: 300 ppm/C; U/M: EA; Value: 115k; EIA_Code: E96; SizeX_mm: 1.0; SizeY_mm: 0.5; SizeZ_mm: 0.6; AEC Qualified: N; VDC_V: 50V; AEC Category: Q200
R32 R39 = CMP-0081856-1: RES, 0, 0%, 0.2 W, AEC-Q200 Grade 0, 0402; Manufacturer: Vishay-Dale; SizeAreaWB_mm2: 3; SizeArea_mm2: 0.5; AEC Qualified: Y; AEC Category: Q200; Value: 0; SizeZ_mm: 0.6; Power_W: 200mW; VDC_V: 50V; Value2: 0.2W; SizeX_mm: 1
R33 = CMP-0023235-5: RES, 680, 1%, 0.1 W, 0603; Manufacturer: Yageo; Power_W: 100mW; TempCo: 100 ppm/C; Value_Code: 680R; Value: 680; SizeX_mm: 1.6; SizeY_mm: 0.8; SizeZ_mm: 1; Value2: 0.1W; SizeArea_mm2: 1.28; AEC Qualified: N; VDC_V: 75V; AEC Category: Q200; SizeAreaWB_mm2: 4.68
R34 = CMP-0026455-2: RES, 576 k, 1%, 0.063 W, AEC-Q200 Grade 0, 0402; Manufacturer: Vishay-Dale; Power_W: 63mW; TempCo: 100 ppm/C; Value: 576k; EIA_Code: E96; SizeX_mm: 1; SizeY_mm: 0.5; SizeZ_mm: 0.6; Value2: 0.063W; AEC Qualified: Y; VDC_V: 50V; AEC Category: Q200; AEC Grade: 0
R35 = CMP-0026543-2: RES, 75.0 k, 1%, 0.063 W, AEC-Q200 Grade 0, 0402; Manufacturer: Vishay-Dale; Power_W: 63mW; TempCo: 100 ppm/C; Value_Code: 75k0; Value: 75.0k; EIA_Code: E96; Res_ohm: 75k; SizeX_mm: 1; SizeY_mm: 0.5; SizeZ_mm: 0.6; Value2: 0.063W; AEC Qualified: Y; VDC_V: 50V; AEC Category: Q200; AEC Grade: 0
R36 = CMP-0026859-2: RES, 1.0 M, 5%, 0.063 W, AEC-Q200 Grade 0, 0402; Manufacturer: Vishay-Dale; Power_W: 63mW; TempCo: 200 ppm/C; Value_Code: 1M00; Value: 1.0Meg; EIA_Code: E24; Res_ohm: 1M; SizeX_mm: 1; SizeY_mm: 0.5; SizeZ_mm: 0.6; Value2: 0.063W; AEC Qualified: Y; VDC_V: 50V; AEC Category: Q200; AEC Grade: 0
R38 = CMP-0023253-5: RES, 6.80 k, 1%, 0.1 W, 0603; Manufacturer: Yageo; Power_W: 100mW; TempCo: 100 ppm/C; Value_Code: 6k80; Value: 6.80k; Res_ohm: 6.8k; SizeX_mm: 1.6; SizeY_mm: 0.8; SizeZ_mm: 1; Value2: 0.1W; SizeArea_mm2: 1.28; AEC Qualified: N; VDC_V: 75V; AEC Category: Q200; SizeAreaWB_mm2: 4.68
R40 = CMP-0078244-2: RES, 30.0 k, 1%, 0.063 W, AEC-Q200 Grade 0, 0402; Manufacturer: Vishay-Dale; Power_W: 63mW; Green_Lifecycle: Active; TempCo: 100 ppm/C; Value_Code: 30k0; Green_REACh: Passed; Value: 30.0k; Res_ohm: 30k; SizeX_mm: 1; SizeY_mm: 0.5; SizeZ_mm: 0.6; Value2: 0.063W; AEC Qualified: Y; VDC_V: 50V; AEC Grade: 0; AEC Category: Q200
R?#1 = CMP-0022986-5: RES, 2.20 k, 1%, 0.1 W, 0603; Manufacturer: Yageo; Power_W: 100mW; TempCo: 100 ppm/C; Value_Code: 2k20; Value: 2.20k; Res_ohm: 2.2k; SizeX_mm: 1.6; SizeY_mm: 0.8; SizeZ_mm: 1; Value2: 0.1W; SizeArea_mm2: 1.28; AEC Qualified: N; VDC_V: 75V; AEC Category: Q200; SizeAreaWB_mm2: 4.68
R?#2 = CMP-0023020-5: RES, 30.0 k, 1%, 0.1 W, 0603; Manufacturer: Yageo; Power_W: 100mW; TempCo: 100 ppm/C; Value_Code: 30k0; Value: 30.0k; Res_ohm: 30k; SizeX_mm: 1.6; SizeY_mm: 0.8; SizeZ_mm: 1; Value2: 0.1W; SizeArea_mm2: 1.28; AEC Qualified: N; VDC_V: 75V; AEC Category: Q200; SizeAreaWB_mm2: 4.68
R?#3 = CMP-0026658-1: RES, 10.0 k, 1%, 0.1 W, 0402; Manufacturer: Panasonic; Power_W: 100mW; TempCo: 100 ppm/C; Value_Code: 10k0; U/M: EA; Value: 10.0k; EIA_Code: E96; Res_ohm: 10k; SizeX_mm: 1; SizeY_mm: 0.5; SizeZ_mm: 0.6; Value2: 0.1W; VDC_V: 50V; AEC Category: Q200
RT1 = CMP-0002523-3: Thermistor NTC, 47k ohm, 5%, 0603; Manufacturer: MuRata; TaMax_C: 125°C; SizeX_mm: 1.6; SizeY_mm: 0.8; TaMin_C: -40°C; Power_W: 100mW; SizeZ_mm: 1; SizeArea_mm2: 1.28; SizeAreaWB_mm2: 4.68; U/M: EA
T2 = CMP-0087465-1: Lm=200uH, Llk=5uH / P:S1:S2:A = 40:10:10:15; Manufacturer: Renco Electronics; AEC Qualified: No; SizeZ_mm: 0.66inch; DCR_ohm: 0.1; Ind_H: 110µH; Ns1toNp: 2.5:0.5:1:0.5:1
U3 = CMP-0860377-2: 4-A/6-A, Single-Channel Reinforced Isolation Gate Driver with High Noise Immunity, DWV0008A (SOIC-8); Manufacturer: Texas Instruments; SizeX_mm: 11.5; SizeArea_mm2: 67.275; SizeAreaWB_mm2: 105.975; CompType: IC; SizeZ_mm: 2.8; SizeY_mm: 5.85; AEC Category: Q200; AEC Qualified: N
U4 = CMP-0086087-1: UCC28781RTW, RTW0024B (WQFN-24); Manufacturer: Texas Instruments; SizeY_mm: 4; SizeZ_mm: 0.8; AEC Category: Q200; SizeArea_mm2: 16; CompType: IC; AEC Qualified: N; SizeAreaWB_mm2: 25
U5 = CMP-0087394-2: Optoisolator Transistor Output 5000Vrms 1 Channel 6-SO; Manufacturer: Toshiba; CTR (Max): 300%; CTR (Min): 100%; SizeZ_mm: 2.3mm
U6 = CMP-0066199-1: 2.5V Low Iq Adjustable Precision Shunt Regulator, DBZ0003A (SOT-23-3); Manufacturer: Texas Instruments; SizeArea_mm2: 7.5; SizeAreaWB_mm2: 14.0; SizeX_mm: 2.5; SizeY_mm: 3.0; SizeZ_mm: 1.12; CompType: IC; U/M: EA
U? = CMP-0033201-3: 0.5% Accuracy Low-Voltage Adjustable Precision Shunt Regulator, DCK0006A (SOT-SC70-6); Manufacturer: Texas Instruments; VO Adj(Max)(V): 6; Initial Accuracy @ 25/deg C(%): 0.5; Eco-Plan: Green (RoHS & no Sb/Br); Iout/Iz(Max)(mA): 15; Rating: Catalog; Temp Coeff(Max)(ppm/ degree C): 129; VO Adj(Min)(V): 1.24; Min Iz for Regulation(uA): 80; AEC Category: Q200; AEC Qualified: N; CompType: IC; SizeAreaWB_mm2: 9.3; SizeArea_mm2: 4.2; SizeX_mm: 2.1; SizeY_mm: 2.0; SizeZ_mm: 1.1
